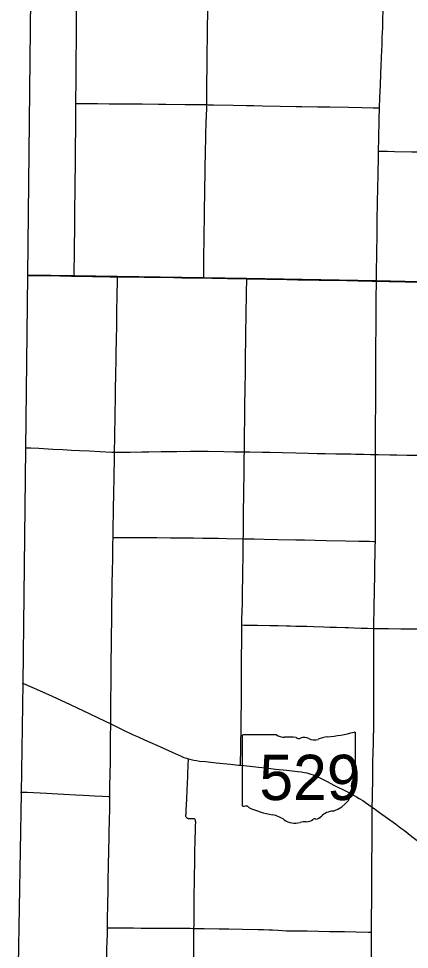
# Model space of a CAD drawing. Extents: x 9078 to 9739, y 4248 to 4966.
# Drawn here: x 9204.9 to 9264.8, y 4556.7 to 4699.7 of the extents above; entities that cross this region are included whole.
import ezdxf

# ---------------------------------------------------------------- set-up
doc = ezdxf.new("R2010")
doc.units = 0
for name, color, linetype in [('GM_X_County', 7, 'Continuous'), ('GM_X_County_Road', 7, 'Continuous'), ('GM_X_State_Route', 7, 'Continuous'), ('GM_X_State_Shield', 7, 'Continuous'), ('GM_X_Township', 7, 'Continuous'), ('GM_X_Township_Road', 7, 'Continuous')]:
    doc.layers.add(name, color=color, linetype=linetype)

msp = doc.modelspace()

# ---------------------------------------------------------------- linework, layer by layer
at = {"layer": 'GM_X_County'}
msp.add_lwpolyline([(9204.85, 4554.27), (9205.29, 4580.7), (9205.57, 4597.6), (9205.96, 4633.56), (9206.25, 4660.25), (9206.81, 4712.2)], dxfattribs=at)
at = {"layer": 'GM_X_County_Road'}
for points in [[(9233.72, 4686.45), (9233.73, 4686.93), (9233.74, 4688.16), (9233.75, 4689.39), (9233.78, 4692.59), (9233.79, 4694.4), (9233.82, 4696.86), (9233.83, 4698.25), (9233.84, 4699.15), (9233.86, 4699.73), (9233.86, 4700.71), (9233.86, 4702.35), (9233.88, 4703.83), (9233.89, 4704.89), (9233.89, 4705.71), (9233.9, 4707.02), (9233.91, 4708.17), (9233.93, 4709.73), (9233.93, 4710.63), (9233.94, 4711.7), (9233.95, 4713.05)], [(9260.22, 4685.95), (9260.28, 4687.48), (9260.36, 4689.45), (9260.43, 4691.25), (9260.48, 4692.4), (9260.53, 4693.63), (9260.58, 4694.86), (9260.61, 4695.59), (9260.63, 4696.17), (9260.65, 4696.74), (9260.68, 4697.48), (9260.71, 4698.3), (9260.73, 4698.79), (9260.75, 4699.44), (9260.78, 4701.08)], [(9233.25, 4659.82), (9233.26, 4660.78), (9233.27, 4662.01), (9233.32, 4666.93), (9233.35, 4668.73), (9233.37, 4670.37), (9233.39, 4671.27), (9233.4, 4671.93), (9233.41, 4672.91), (9233.43, 4674.06), (9233.45, 4675.37), (9233.49, 4677.42), (9233.51, 4678.49), (9233.53, 4679.64), (9233.57, 4680.87), (9233.6, 4681.93), (9233.65, 4683.65), (9233.71, 4685.87), (9233.72, 4686.45)], [(9233.72, 4686.45), (9233.91, 4686.44), (9234.73, 4686.42), (9237.76, 4686.36), (9239.81, 4686.32), (9240.96, 4686.29), (9242.27, 4686.27), (9244.97, 4686.22), (9247.43, 4686.17), (9248.33, 4686.16), (9250.71, 4686.12), (9252.59, 4686.09), (9255.46, 4686.05), (9257.51, 4686.01), (9259.23, 4685.98), (9259.97, 4685.97), (9260.22, 4685.95)], [(9260.09, 4679.31), (9260.12, 4681.25), (9260.14, 4682.15), (9260.16, 4683.22), (9260.18, 4684.28), (9260.22, 4685.84), (9260.22, 4685.95)], [(9259.74, 4659.34), (9259.74, 4659.52), (9259.77, 4661.24), (9259.8, 4662.96), (9259.82, 4664.44), (9259.84, 4665.67), (9259.86, 4667.31), (9259.89, 4669.03), (9259.93, 4671.08), (9259.98, 4674.03), (9260.01, 4675.26), (9260.04, 4676.58), (9260.05, 4677.64), (9260.08, 4678.95), (9260.09, 4679.31)], [(9206.26, 4660.22), (9206.94, 4660.21), (9208.1, 4660.2), (9211.15, 4660.15), (9212.96, 4660.12), (9213.4, 4660.12)], [(9213.4, 4660.12), (9214.04, 4660.1), (9216.18, 4660.07), (9218.88, 4660.02), (9220.01, 4660.02)], [(9220.01, 4660.02), (9220.69, 4660.01), (9222.08, 4659.99), (9223.23, 4659.98), (9224.13, 4659.96), (9225.61, 4659.94), (9228.64, 4659.89), (9229.87, 4659.87), (9231.1, 4659.86), (9232.25, 4659.84), (9233.25, 4659.82)], [(9233.25, 4659.82), (9234.55, 4659.8), (9235.69, 4659.78), (9236.92, 4659.76), (9238.81, 4659.73), (9239.87, 4659.71)], [(9239.87, 4659.71), (9242.91, 4659.66), (9244.55, 4659.62), (9246.03, 4659.6), (9247.67, 4659.56), (9250.95, 4659.5), (9251.93, 4659.49), (9253, 4659.47), (9255.21, 4659.43), (9256.93, 4659.4), (9259.06, 4659.35), (9259.74, 4659.34)], [(9259.61, 4632.72), (9259.61, 4633.6), (9259.62, 4634.67), (9259.62, 4635.08), (9259.62, 4635.65), (9259.63, 4636.47), (9259.63, 4638.11), (9259.63, 4638.44), (9259.64, 4639.26), (9259.64, 4642.7), (9259.65, 4644.42), (9259.67, 4647.46), (9259.67, 4649.1), (9259.7, 4652.46), (9259.71, 4654.35), (9259.72, 4656.15), (9259.73, 4657.38), (9259.74, 4658.53), (9259.74, 4659.34)], [(9259.74, 4659.34), (9261.69, 4659.3), (9264.23, 4659.25), (9266.12, 4659.21), (9266.39, 4659.2)], [(9219.34, 4619.98), (9219.34, 4620), (9219.36, 4621.15), (9219.38, 4622.3), (9219.39, 4623.03), (9219.42, 4624.92), (9219.44, 4626.23), (9219.46, 4627.38), (9219.49, 4628.52), (9219.5, 4629.34), (9219.52, 4630.08), (9219.54, 4631.39), (9219.57, 4632.79), (9219.58, 4633.08)], [(9219.58, 4633.08), (9220.65, 4633.07), (9221.96, 4633.08), (9223.77, 4633.11), (9224.84, 4633.13), (9226.73, 4633.15), (9227.87, 4633.17), (9229.11, 4633.17), (9231.24, 4633.2), (9232.72, 4633.2), (9233.95, 4633.2), (9236.33, 4633.16), (9237.98, 4633.13), (9239.49, 4633.12)], [(9239.32, 4619.78), (9239.33, 4620.21), (9239.35, 4621.19), (9239.35, 4621.68), (9239.36, 4622.34), (9239.36, 4622.83), (9239.38, 4624.47), (9239.4, 4625.95), (9239.42, 4627.18), (9239.44, 4629.73), (9239.48, 4632.36), (9239.49, 4633.12)], [(9259.59, 4619.35), (9259.59, 4619.41), (9259.59, 4619.9), (9259.59, 4620.72), (9259.59, 4621.46), (9259.59, 4623.92), (9259.6, 4625.97), (9259.59, 4626.88), (9259.59, 4627.28), (9259.59, 4627.86), (9259.6, 4628.51), (9259.6, 4629.91), (9259.61, 4632.37), (9259.61, 4632.72)], [(9219.08, 4603.12), (9219.08, 4603.2), (9219.1, 4604.92), (9219.13, 4607.22), (9219.14, 4608.61), (9219.16, 4609.76), (9219.2, 4611.56), (9219.21, 4612.95), (9219.24, 4614.76), (9219.28, 4616.8), (9219.3, 4617.79), (9219.32, 4618.94), (9219.34, 4619.98)], [(9239.1, 4606.53), (9239.12, 4607.32), (9239.16, 4608.71), (9239.18, 4609.78), (9239.2, 4610.52), (9239.22, 4611.58), (9239.26, 4613.97), (9239.27, 4615.28), (9239.29, 4616.51), (9239.32, 4619.22), (9239.32, 4619.78)], [(9239.32, 4619.78), (9239.6, 4619.77), (9239.92, 4619.77), (9240.99, 4619.75), (9242.55, 4619.71), (9244.6, 4619.66), (9247.39, 4619.6), (9248.7, 4619.58), (9250.34, 4619.55), (9252.06, 4619.51), (9255.01, 4619.44), (9257.06, 4619.4), (9258.71, 4619.38), (9259.36, 4619.36), (9259.59, 4619.35)], [(9259.35, 4606), (9259.36, 4606.54), (9259.37, 4606.95), (9259.37, 4607.6), (9259.38, 4608.01), (9259.41, 4609.16), (9259.43, 4610.06), (9259.45, 4611.05), (9259.46, 4611.95), (9259.49, 4614.08), (9259.51, 4614.98), (9259.53, 4616.05), (9259.55, 4617.12), (9259.57, 4618.59), (9259.59, 4619.35)], [(9239.1, 4606.53), (9239.45, 4606.52), (9240.27, 4606.5), (9241.5, 4606.48), (9243.39, 4606.45), (9244.7, 4606.43), (9245.93, 4606.4), (9246.59, 4606.39), (9247.41, 4606.36), (9248.15, 4606.34), (9249.05, 4606.32), (9250.12, 4606.29), (9251.67, 4606.24), (9252.58, 4606.21), (9253.64, 4606.18), (9254.95, 4606.14), (9255.45, 4606.12), (9256.35, 4606.1), (9257.41, 4606.06), (9258.4, 4606.03), (9259.35, 4606)], [(9259.11, 4578.52), (9259.12, 4578.97), (9259.14, 4579.64), (9259.16, 4581.12), (9259.18, 4582.18), (9259.2, 4583.74), (9259.21, 4585.38), (9259.24, 4586.94), (9259.28, 4588.42), (9259.31, 4589.56), (9259.33, 4590.3), (9259.34, 4591.2), (9259.35, 4592.68), (9259.35, 4593.58), (9259.34, 4595.55), (9259.34, 4596.86), (9259.34, 4598.5), (9259.34, 4599.98), (9259.34, 4600.88), (9259.35, 4601.29), (9259.35, 4602.27), (9259.35, 4603.26), (9259.34, 4605.39), (9259.34, 4605.88), (9259.35, 4606)], [(9259.35, 4606), (9259.63, 4605.99), (9260.45, 4605.98), (9261.59, 4605.96), (9263.48, 4605.94), (9264.88, 4605.93), (9266.44, 4605.91), (9267.75, 4605.9), (9268.82, 4605.89), (9270.05, 4605.88), (9270.95, 4605.87), (9272.43, 4605.84), (9274.31, 4605.81), (9276.12, 4605.77), (9276.36, 4605.77)], [(9218.99, 4591.32), (9218.98, 4592.22), (9219.01, 4595.09), (9219.03, 4597.54), (9219.04, 4598.94), (9219.05, 4600.09), (9219.06, 4601.23), (9219.08, 4603.12)]]:
    msp.add_lwpolyline(points, dxfattribs=at)
at = {"layer": 'GM_X_State_Route'}
for points in [[(9205.37, 4597.66), (9206.17, 4597.3), (9207.59, 4596.66), (9209.99, 4595.59), (9211.41, 4594.95), (9212.68, 4594.36), (9213.94, 4593.76), (9215.57, 4592.98), (9217.05, 4592.27), (9218.99, 4591.32), (9219.71, 4590.98), (9220.73, 4590.49), (9222.43, 4589.67), (9223.18, 4589.34), (9224.15, 4588.9), (9224.98, 4588.53), (9226.17, 4587.99), (9228.41, 4586.97), (9229.77, 4586.38), (9230.22, 4586.19), (9230.61, 4586.05), (9230.92, 4585.95), (9231.32, 4585.85), (9231.72, 4585.76), (9232.13, 4585.69), (9232.62, 4585.63), (9233.51, 4585.53), (9235.15, 4585.36), (9237.35, 4585.14), (9238.58, 4585.01), (9238.91, 4584.98), (9240.37, 4584.82), (9241.68, 4584.68), (9242.82, 4584.56), (9244.29, 4584.4), (9246, 4584.22), (9247.63, 4584.03), (9248.2, 4583.96), (9248.69, 4583.88), (9249.09, 4583.79), (9249.4, 4583.71), (9249.71, 4583.61), (9250.02, 4583.5), (9250.4, 4583.34), (9250.77, 4583.18), (9251.36, 4582.88), (9252.09, 4582.51), (9253.33, 4581.87), (9255.09, 4580.98), (9255.96, 4580.52), (9256.68, 4580.13), (9257.11, 4579.89), (9257.66, 4579.54), (9258.07, 4579.27), (9259.11, 4578.52), (9259.6, 4578.17), (9260.2, 4577.73), (9262.67, 4575.96), (9262.95, 4575.76)], [(9262.95, 4575.76), (9263.47, 4575.39), (9264.06, 4574.95), (9264.64, 4574.49), (9265.21, 4574.02), (9265.78, 4573.56), (9266.24, 4573.21), (9266.71, 4572.87), (9267.25, 4572.5), (9268.01, 4572.01), (9268.22, 4571.87)]]:
    msp.add_lwpolyline(points, dxfattribs=at)
at = {"layer": 'GM_X_State_Shield'}
for p, q in [((9239.13, 4589.45), (9239.13, 4578.89)), ((9244.4, 4589.63), (9239.31, 4589.63)), ((9256.54, 4584.37), (9256.54, 4589.9)), ((9256.53, 4584.37), (9256.54, 4584.37))]:
    msp.add_line(p, q, dxfattribs=at)
for centre, major_axis, start_param, end_param in [((9239.33, 4589.47), (0.202, 0), 1.712693, 3.28349), ((9245.62, 4590.86), (1.96, 0), 4.042523, 4.731795), ((9246.26, 4583.7), (7.02, 0), 1.404758, 1.657858), ((9247.86, 4589.53), (0.564, 0), 3.836095, 5.185415), ((9248.69, 4588.31), (1.17, 0), 0.950623, 2.079405), ((9252.69, 4586.41), (3.71, 0), 1.699011, 2.107814), ((9250.34, 4604.04), (18.45, 0), 4.814394, 5.042369), ((9256.34, 4589.92), (0.194, 0), 6.141152, 7.989035), ((9250.2, 4589.98), (1.41, 0), 4.081561, 5.145723), ((9256.49, 4583.96), (0.3, 0), 1.883978, 3.671073), ((9254.58, 4583.26), (1.8, 0), 5.934695, 6.695948), ((9256.33, 4584.35), (0.207, 0), 5.05454, 6.418171), ((9257.23, 4582.06), (1.31, 0), 2.387724, 3.262537), ((9251.37, 4581.35), (4.62, 0), 5.101752, 6.440018), ((9239.34, 4578.86), (0.203, 0), 3.00124, 4.508301), ((9239.37, 4579.94), (1.55, 0), 4.665946, 4.897461), ((9239.68, 4578.28), (0.56, 0), 0.519207, 1.627899), ((9246.75, 4587.77), (13.33, 0), 4.195997, 4.488961), ((9253.32, 4575.92), (2.53, 0), 1.647645, 2.488434), ((9242.78, 4574.14), (4.17, 0), 0.823519, 1.323587), ((9247.29, 4578.22), (2.65, 0), 4.026481, 4.996735), ((9248.81, 4574.57), (2.17, 0), 1.495662, 1.94098), ((9249.01, 4577.43), (1.41, 0), 4.691044, 5.507374), ((9250.28, 4576.41), (0.397, 0), 1.147584, 2.315152), ((9250.11, 4577.86), (1.49, 0), 4.937069, 5.64225)]:
    msp.add_ellipse(centre, major_axis=major_axis, ratio=0.8, start_param=start_param, end_param=end_param, dxfattribs=at)
at = {"layer": 'GM_X_Township'}
msp.add_lwpolyline([(9313.41, 4711.5), (9313.22, 4698.18), (9312.91, 4676.33), (9312.65, 4658.23), (9286.19, 4658.81), (9266.36, 4659.24), (9259.71, 4659.36), (9239.86, 4659.74), (9233.22, 4659.86), (9219.98, 4660.05), (9213.36, 4660.13), (9206.25, 4660.25)], dxfattribs=at)
at = {"layer": 'GM_X_Township_Road'}
for points in [[(9213.65, 4686.64), (9213.65, 4687.48), (9213.66, 4689.53), (9213.67, 4690.77), (9213.69, 4692.98), (9213.7, 4694.37), (9213.71, 4695.36), (9213.72, 4696.26), (9213.73, 4697.98), (9213.74, 4700.03), (9213.74, 4701.35), (9213.75, 4703.81), (9213.76, 4705.37), (9213.76, 4706.52), (9213.77, 4709.14), (9213.78, 4711.44), (9213.77, 4712.26), (9213.78, 4712.59)], [(9213.4, 4660.12), (9213.39, 4660.6), (9213.43, 4663.71), (9213.44, 4664.86), (9213.44, 4665.51), (9213.45, 4666.49), (9213.46, 4667.72), (9213.47, 4668.62), (9213.49, 4670.01), (9213.53, 4673.54), (9213.55, 4674.93), (9213.57, 4676.74), (9213.58, 4678.13), (9213.59, 4679.77), (9213.6, 4680.92), (9213.62, 4681.82), (9213.64, 4682.97), (9213.64, 4684.12), (9213.65, 4685.68), (9213.65, 4686.64)], [(9213.65, 4686.64), (9213.84, 4686.63), (9214.01, 4686.63), (9214.74, 4686.63), (9215.64, 4686.62), (9216.95, 4686.6), (9218.76, 4686.59), (9222.69, 4686.56), (9223.83, 4686.55), (9226.29, 4686.52), (9227.44, 4686.51), (9230.39, 4686.49), (9231.62, 4686.47), (9233.72, 4686.45)], [(9260.09, 4679.31), (9260.32, 4679.3), (9260.4, 4679.3), (9261.47, 4679.28), (9262.53, 4679.26), (9265.16, 4679.22), (9266.06, 4679.21), (9266.64, 4679.2), (9268.53, 4679.17), (9268.73, 4679.17)], [(9219.58, 4633.08), (9219.58, 4633.8), (9219.59, 4634.7), (9219.62, 4636.09), (9219.62, 4636.83), (9219.64, 4637.4), (9219.66, 4638.71), (9219.71, 4641.66), (9219.74, 4643.13), (9219.76, 4644.52), (9219.79, 4645.59), (9219.81, 4646.65), (9219.83, 4648.46), (9219.86, 4650.18), (9219.9, 4652.72), (9219.92, 4654.44), (9219.97, 4657.38), (9220, 4659.19), (9220, 4659.83), (9220, 4659.84), (9220.01, 4660.02)], [(9239.49, 4633.12), (9239.51, 4635.51), (9239.52, 4636.41), (9239.54, 4637.64), (9239.56, 4639.11), (9239.58, 4640.43), (9239.61, 4642.56), (9239.62, 4643.71), (9239.64, 4644.45), (9239.66, 4646.41), (9239.68, 4648.06), (9239.7, 4650.02), (9239.73, 4652.16), (9239.74, 4653.3), (9239.76, 4654.86), (9239.81, 4656.83), (9239.83, 4657.82), (9239.86, 4659.43), (9239.86, 4659.54), (9239.87, 4659.71)], [(9205.88, 4633.73), (9206.73, 4633.73), (9207.96, 4633.67), (9210.09, 4633.55), (9211.64, 4633.47), (9212.95, 4633.39), (9214.18, 4633.33), (9215.65, 4633.25), (9217.37, 4633.16), (9219.14, 4633.09), (9219.58, 4633.08)], [(9239.49, 4633.12), (9240.31, 4633.1), (9242.28, 4633.07), (9243.43, 4633.05), (9245.32, 4633.01), (9247.37, 4632.97), (9249.26, 4632.91), (9250.65, 4632.88), (9251.88, 4632.85), (9253.52, 4632.83), (9254.42, 4632.82), (9255.82, 4632.79), (9256.56, 4632.77), (9257.22, 4632.75), (9257.3, 4632.75), (9257.8, 4632.74), (9258.86, 4632.72), (9259.44, 4632.72), (9259.61, 4632.72)], [(9259.61, 4632.72), (9260.01, 4632.72), (9261.82, 4632.68), (9262.88, 4632.66), (9264.44, 4632.63), (9266, 4632.6), (9268.46, 4632.55), (9269.44, 4632.52), (9269.59, 4632.52)], [(9219.34, 4619.98), (9219.6, 4619.98), (9219.69, 4619.98), (9220.83, 4619.97), (9221.74, 4619.97), (9223.87, 4619.96), (9224.93, 4619.95), (9226.08, 4619.94), (9228.13, 4619.92), (9229.52, 4619.92), (9231.66, 4619.89), (9233.13, 4619.88), (9235.51, 4619.84), (9236.82, 4619.82), (9239.32, 4619.78)], [(9238.91, 4584.98), (9238.91, 4585.23), (9238.92, 4585.81), (9238.94, 4586.87), (9238.96, 4588.02), (9239, 4590.73), (9239.01, 4591.71), (9239.02, 4592.94), (9239.03, 4593.92), (9239.04, 4595.56), (9239.04, 4596.63), (9239.04, 4597.2), (9239.03, 4598.11), (9239.04, 4599.09), (9239.05, 4599.66), (9239.06, 4600.98), (9239.06, 4601.79), (9239.08, 4603.76), (9239.09, 4605.89), (9239.1, 4606.53)], [(9218.86, 4580.16), (9218.86, 4580.96), (9218.87, 4581.78), (9218.9, 4583.58), (9218.93, 4585.55), (9218.94, 4586.86), (9218.95, 4588.09), (9218.97, 4589.65), (9218.99, 4590.88), (9218.99, 4591.32)], [(9230.69, 4580.67), (9230.71, 4581.21), (9230.8, 4583.25), (9230.83, 4583.99), (9230.84, 4584.57), (9230.88, 4585.22), (9230.91, 4585.71), (9230.92, 4585.95)], [(9205.12, 4580.85), (9206.16, 4580.85), (9209.11, 4580.69), (9211.73, 4580.55), (9213.62, 4580.46), (9214.77, 4580.4), (9215.67, 4580.35), (9216.49, 4580.3), (9217.72, 4580.23), (9218.62, 4580.18), (9218.7, 4580.17), (9218.86, 4580.16)], [(9231.75, 4559.92), (9231.76, 4560.39), (9231.77, 4561.3), (9231.79, 4562.69), (9231.8, 4563.92), (9231.81, 4565.07), (9231.84, 4567.04), (9231.85, 4568.02), (9231.86, 4568.6), (9231.87, 4569.33), (9231.88, 4569.83), (9231.89, 4570.15), (9231.89, 4570.81), (9231.91, 4571.47), (9231.96, 4573.6), (9231.98, 4574.91), (9232, 4575.65), (9232.02, 4576.22), (9232.01, 4576.39), (9232.01, 4576.47), (9231.99, 4576.56), (9231.95, 4576.65), (9231.91, 4576.7), (9231.85, 4576.74), (9231.77, 4576.76), (9231.68, 4576.77), (9231.1, 4576.76), (9230.94, 4576.77), (9230.86, 4576.78), (9230.78, 4576.81), (9230.71, 4576.84), (9230.64, 4576.9), (9230.59, 4576.96), (9230.56, 4577.03), (9230.53, 4577.11), (9230.52, 4577.19), (9230.53, 4577.36), (9230.54, 4577.52), (9230.58, 4578.18), (9230.61, 4578.83), (9230.65, 4579.81), (9230.67, 4580.3), (9230.69, 4580.67)], [(9218.5, 4560.01), (9218.51, 4560.38), (9218.51, 4561.77), (9218.52, 4563.17), (9218.58, 4566.2), (9218.6, 4567.76), (9218.63, 4569.07), (9218.65, 4570.22), (9218.67, 4571.28), (9218.7, 4572.43), (9218.72, 4573.33), (9218.74, 4574.81), (9218.77, 4576.37), (9218.83, 4578.42), (9218.85, 4579.89), (9218.86, 4580.16)], [(9259.02, 4559.34), (9259.02, 4559.7), (9259.02, 4560.44), (9259.02, 4561.75), (9259.04, 4564.05), (9259.04, 4564.7), (9259.04, 4565.61), (9259.05, 4566.34), (9259.06, 4567.49), (9259.06, 4568.56), (9259.07, 4570.03), (9259.08, 4573.06), (9259.08, 4574.13), (9259.09, 4574.7), (9259.09, 4575.61), (9259.1, 4576.67), (9259.11, 4577.74), (9259.11, 4578.23), (9259.11, 4578.52)], [(9218.36, 4553.27), (9218.36, 4553.33), (9218.37, 4554.15), (9218.39, 4555.29), (9218.41, 4556.85), (9218.44, 4557.92), (9218.47, 4558.98), (9218.49, 4559.8), (9218.5, 4560.01)], [(9218.5, 4560.01), (9218.71, 4560.01), (9220.02, 4559.99), (9221.5, 4559.99), (9222.48, 4559.99), (9223.63, 4559.98), (9224.37, 4559.97), (9224.94, 4559.97), (9225.76, 4559.97), (9226.91, 4559.97), (9227.73, 4559.96), (9228.63, 4559.96), (9229.86, 4559.95), (9230.35, 4559.94), (9231.17, 4559.93), (9231.75, 4559.92)], [(9231.68, 4542.43), (9231.67, 4542.85), (9231.66, 4544.32), (9231.66, 4545.38), (9231.66, 4546.04), (9231.68, 4548.5), (9231.69, 4549.07), (9231.71, 4550.96), (9231.72, 4553.09), (9231.71, 4554), (9231.71, 4554.65), (9231.72, 4555.88), (9231.71, 4556.79), (9231.72, 4557.61), (9231.74, 4559.25), (9231.75, 4559.92)], [(9231.75, 4559.92), (9232.16, 4559.92), (9233.3, 4559.9), (9235.6, 4559.86), (9237.08, 4559.83), (9239.21, 4559.79), (9241.59, 4559.74), (9242.41, 4559.73), (9243.31, 4559.71), (9243.8, 4559.7), (9244.7, 4559.65), (9245.93, 4559.57), (9246.34, 4559.55), (9246.83, 4559.55), (9247.73, 4559.56), (9249.13, 4559.54), (9250.85, 4559.49), (9252.57, 4559.46), (9253.55, 4559.45), (9254.87, 4559.42), (9256.59, 4559.39), (9258.55, 4559.35), (9259.02, 4559.34)], [(9258.96, 4554.2), (9258.96, 4554.3), (9258.97, 4554.54), (9258.99, 4555.28), (9259.01, 4557.66), (9259.01, 4558.39), (9259.02, 4559.34)]]:
    msp.add_lwpolyline(points, dxfattribs=at)

# ---------------------------------------------------------------- texts
at = {"layer": 'GM_X_State_Shield'}
msp.add_text('529', height=6.961, dxfattribs=at).set_placement((9241.79, 4579.63))

doc.saveas('drawing.dxf')
